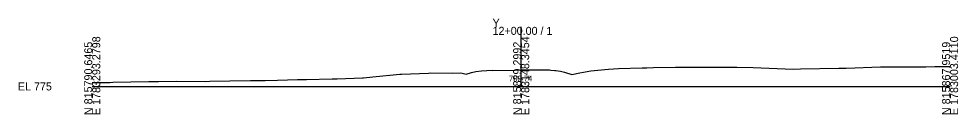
# Model space of a CAD drawing. Extents: x -12583 to 5303, y -44 to 25667.
# Drawn here: x -25.7 to 302.8, y 1490.3 to 1523.6 of the extents above; entities that cross this region are included whole.
import ezdxf

# ---------------------------------------------------------------- set-up
doc = ezdxf.new("R2010")
doc.units = 0
for name, color, linetype in [('Exist Cross Section Cell', 7, 'Continuous'), ('Exist XS Center Line Elevation Label', 7, 'Continuous'), ('Exist XS Ground Line', 7, 'Continuous')]:
    doc.layers.add(name, color=color, linetype=linetype)

msp = doc.modelspace()

# ---------------------------------------------------------------- linework, layer by layer
at = {"layer": 'Exist Cross Section Cell'}
for p, q in [((150, 1500), (150, 1520.8)), ((0, 1500), (150, 1500)), ((150, 1500), (300, 1500))]:
    msp.add_line(p, q, dxfattribs=at)
at = {"layer": 'Exist XS Ground Line'}
for p, q in [((117.56, 1504.64), (118.42, 1504.69)), ((118.42, 1504.69), (125.92, 1504.68)), ((125.92, 1504.68), (128.93, 1504.69)), ((128.93, 1504.69), (130.78, 1504.27)), ((130.78, 1504.27), (132.67, 1504.89)), ((132.67, 1504.89), (134.15, 1505.21)), ((134.15, 1505.21), (136.18, 1505.43)), ((136.18, 1505.43), (139.85, 1505.68)), ((139.85, 1505.68), (139.87, 1505.5)), ((139.87, 1505.5), (147.94, 1505.69)), ((147.94, 1505.69), (149.84, 1505.74)), ((149.84, 1505.74), (153.63, 1505.74)), ((153.63, 1505.74), (154.46, 1505.74)), ((154.46, 1505.74), (159.88, 1505.76)), ((159.88, 1505.76), (160.38, 1505.71)), ((160.38, 1505.71), (161.75, 1505.55)), ((161.75, 1505.55), (162.07, 1505.52)), ((162.07, 1505.52), (163.77, 1505.33)), ((163.77, 1505.33), (165.12, 1504.93)), ((165.12, 1504.93), (167.68, 1504.2)), ((167.68, 1504.2), (170.57, 1504.72)), ((170.57, 1504.72), (174.31, 1505.45)), ((174.31, 1505.45), (180.55, 1505.97)), ((180.55, 1505.97), (184.07, 1506.24)), ((184.07, 1506.24), (192.3, 1506.47)), ((192.3, 1506.47), (193.92, 1506.52)), ((193.92, 1506.52), (196.33, 1506.57)), ((196.33, 1506.57), (203.96, 1506.69)), ((203.96, 1506.69), (209.29, 1506.69)), ((209.29, 1506.69), (212.38, 1506.71)), ((212.38, 1506.71), (217.79, 1506.68)), ((217.79, 1506.68), (225.37, 1506.73)), ((225.37, 1506.73), (231.11, 1506.56)), ((231.11, 1506.56), (245.12, 1506.08)), ((245.12, 1506.08), (247.66, 1506.17)), ((247.66, 1506.17), (261.06, 1506.4)), ((261.06, 1506.4), (262.09, 1506.38)), ((262.09, 1506.38), (263.61, 1506.42)), ((263.61, 1506.42), (275.72, 1506.83)), ((275.72, 1506.83), (281.93, 1506.83)), ((281.93, 1506.83), (291.46, 1506.89)), ((291.46, 1506.89), (294.63, 1506.9)), ((294.63, 1506.9), (300, 1506.93)), ((0, 1501.38), (6.09, 1501.42)), ((6.09, 1501.42), (7.18, 1501.45)), ((7.18, 1501.45), (19.82, 1501.71)), ((19.82, 1501.71), (21.41, 1501.73)), ((21.41, 1501.73), (23.12, 1501.75)), ((23.12, 1501.75), (29.57, 1501.83)), ((29.57, 1501.83), (39.48, 1501.77)), ((39.48, 1501.77), (41.1, 1501.8)), ((41.1, 1501.8), (48.07, 1502)), ((48.07, 1502), (55.31, 1502.04)), ((55.31, 1502.04), (57.42, 1502.04)), ((57.42, 1502.04), (60.42, 1502.12)), ((60.42, 1502.12), (64.8, 1502.22)), ((64.8, 1502.22), (71.78, 1502.43)), ((71.78, 1502.43), (74.97, 1502.37)), ((74.97, 1502.37), (83.93, 1502.59)), ((83.93, 1502.59), (84.95, 1502.63)), ((84.95, 1502.63), (85.64, 1502.64)), ((85.64, 1502.64), (94.53, 1502.96)), ((94.53, 1502.96), (94.84, 1502.99)), ((94.84, 1502.99), (98.07, 1503.38)), ((98.07, 1503.38), (107.54, 1504.22)), ((107.54, 1504.22), (108.12, 1504.28)), ((108.12, 1504.28), (117.56, 1504.64))]:
    msp.add_line(p, q, dxfattribs=at)

# ---------------------------------------------------------------- texts
at = {"layer": 'Exist Cross Section Cell'}
for s, p in [('Y', (140, 1520.8)), ('12+00.00 / 1', (140, 1518)), ('EL 775', (-26, 1498.6))]:
    msp.add_text(s, height=2.8, dxfattribs=at).set_placement(p)
for s, p in [('N 815790.6465', (0, 1490)), ('E 1783293.2798', (2.8, 1490)), ('N 815829.2992', (150, 1490)), ('E 1783148.3454', (152.8, 1490)), ('N 815867.9519', (300, 1490)), ('E 1783003.4110', (302.8, 1490))]:
    msp.add_text(s, height=2.8, rotation=90, dxfattribs=at).set_placement(p)
at = {"layer": 'Exist XS Center Line Elevation Label'}
msp.add_text('780.74', height=2, dxfattribs=at).set_placement((145.72, 1501.74))

doc.saveas('drawing.dxf')
